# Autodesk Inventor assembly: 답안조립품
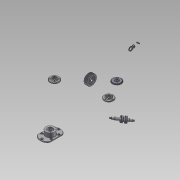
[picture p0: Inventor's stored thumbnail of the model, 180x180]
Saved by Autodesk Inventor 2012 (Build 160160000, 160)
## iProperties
Created: 2015-02
Part Number: 답안조립품
Document SubType Name: Assembly
Designer: Administrator
Author: Administrator
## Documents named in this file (12)
- C:\Documents and Settings\Administrator\바탕 화면\450207V1005\답안조립품.iam
- C:\Documents and Settings\Administrator\바탕 화면\450207V1005\2-커버.ipt
- C:\Documents and Settings\Administrator\바탕 화면\450207V1005\3-축.ipt
- C:\Documents and Settings\Administrator\바탕 화면\450207V1005\4-V벨트풀리.ipt
- C:\Documents and Settings\Administrator\바탕 화면\450207V1005\5-체인 스프로킷.ipt
- C:\Documents and Settings\Administrator\바탕 화면\450207V1005\6-베어링 6206.ipt
- C:\Documents and Settings\Administrator\바탕 화면\450207V1005\7-부시.ipt
- C:\Documents and Settings\Administrator\바탕 화면\450207V1005\8-오일실 30x42.ipt
- C:\Documents and Settings\Administrator\바탕 화면\450207V1005\9-M16-너트.ipt
- C:\Documents and Settings\Administrator\바탕 화면\450207V1005\10-M6.ipt
- C:\Documents and Settings\Administrator\바탕 화면\450207V1005\11-키 6x6.ipt
- C:\Documents and Settings\Administrator\바탕 화면\450207V1005\부품1.ipt
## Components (12 placed, 10 different names)
1. 3-축:1
2. 4-V벨트풀리:1
3. 5-체인 스프로킷:1
4. 6-베어링 6206:1
5. 7-부시:1
6. 8-8-오일실 30x42:1
7. 9-M16 너트:1
8. 10-M6:1
9. 11-키 6x6:1
10. 2-커버:2
11. 2-커버:3
12. 6-베어링 6206:2
